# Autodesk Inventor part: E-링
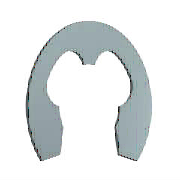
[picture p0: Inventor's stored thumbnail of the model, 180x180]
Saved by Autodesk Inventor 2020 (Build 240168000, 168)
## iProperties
IsCustomPart: 1
Created: 2012-02
Part Number: E-링
Material: 강철, 연강
Description: 일반용 테이퍼 및 줄어든 횡단면 리테이닝 링 - E-링 외부 시리즈 3CM1 리테이닝 링
Document SubType Name: Modeling
Standard: ANSI B27.7
Designer: mduedu
Standard Revision: 1999
Standards Organization: ANSI
Language: ko-KR
Size Designation: 6
Categories: <MemberInstance><Categories><Category DisplayName="샤프트 부품" InternalName="7f7aeb1f-a693-4053-b835-cee3144e0d98" Mnemonic="SHFT"><Category DisplayName="써클립" Inter
Density: 1 g/cm^3
Appearance: 파란색 - 벽 페인트 - 광택
Author: mduedu
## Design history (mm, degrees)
sketch "스케치1"
  geometry: L1 (-0.485, 0.024)-(0, 0.024) reference; L2 (-3.206, 0)-(3.486, 0) reference; L3 (-2.223, -3.946)-(2.223, -3.946); L4 (0, 1.949)-(0, -3.479) reference; L5 (-2.91, -2.006)-(-2.435, -2.006); L6 (-0.485, -0.066)-(-0.485, 0.405); L7 (0, 2.574)-(2.53, 2.574); L8 (-2.223, -3.946)-(-3.022, -6.291); L9 (0, -0.551)-(-1.278, -0.551); L10 (2.223, -3.946)-(3.022, -6.291); L11 (2.91, -2.006)-(2.435, -2.006); L12 (0.485, -0.066)-(0.485, 0.405); C1 r 3 at (0, -2.976); A1 r 2.425 centre (0, -2.976) between (-2.297, -2.199) and (-2.223, -3.946); A2 r 0.485 centre (0, -0.066) between (-0.485, -0.066) and (0.485, -0.066); A3 r 5.55 centre (0, -2.976) between (4.27, -6.521) and (-4.27, -6.521); A4 r 3.88 centre (0, -2.976) between (-0.97, 0.78) and (-3.424, -1.15); A5 r 0.388 centre (-0.873, 0.405) between (-0.485, 0.405) and (-0.97, 0.78); A6 r 0.582 centre (-2.91, -1.424) between (-3.424, -1.15) and (-2.91, -2.006); A7 r 0.145 centre (-2.435, -2.152) between (-2.297, -2.199) and (-2.435, -2.006); A8 r 0.727 centre (-3.711, -6.057) between (-4.27, -6.521) and (-3.022, -6.291); A9 r 0.727 centre (3.711, -6.057) between (3.022, -6.291) and (4.27, -6.521); A10 r 2.425 centre (0, -2.976) between (2.223, -3.946) and (2.297, -2.199); A11 r 0.145 centre (2.435, -2.152) between (2.435, -2.006) and (2.297, -2.199); A12 r 0.582 centre (2.91, -1.424) between (2.91, -2.006) and (3.424, -1.15); A13 r 3.88 centre (0, -2.976) between (3.424, -1.15) and (0.97, 0.78); A14 r 0.388 centre (0.873, 0.405) between (0.97, 0.78) and (0.485, 0.405); 1 further point
  constraints: 30 point on circle, 20 end point, 15 centre point, 13 symmetric about line, 12 tangent, 8 point on line, 4 parallel, 2 coincident, 2 horizontal, 1 concentric, 1 perpendicular, 1 vertical alignment, 9 other
  dimensions: "d0" = 6 diameter of C1 (= WD); "d3" = 0.97 distance from line of A1.centre L3 (= 0.2 x ND); "d4" = 0.485 radius of A2 (= 0.1 x ND); "d5" = 11.1 diameter of A3 (= SD2); "d8" = 3.88 radius of A4 (= 0.8 x ND); "d9" = 0.97 distance from line of A1.centre L5 (= 0.2 x ND); "d10" = 0.388 radius of A5 (= 0.08 x ND); "d11" = 0.582 radius of A6 (= 0.12 x ND); "d12" = 0.1455 radius of A7 (= 0.03 x ND); "d13" = 0.7275 radius of A8 (= 0.15 x ND); "d14" = 2.425 distance from line of A1.centre L9 (= 0.5 x ND); "d15" = 2.425 radius of A1 (= 0.5 x ND)
extrude "본체" new body sketch "스케치1" distance "d16" = 0.6 (= SD); taper "d17" = 0 deg
workaxis "Work Axis1"
workaxis "Work Axis2"
workplane "Work Plane1"
body "Solid1"
other parameters: "ND" = 4.85 [user parameter; used in 14 equation terms], "SD" = 0.6 [user parameter; used in 1 equation term], "WD" = 6 (= WDMIN) [user parameter; used in 1 equation term], "d1" = 7.76 (= 1.6 x ND), "d2" = 4.85 (= ND), "SD2" = 11.1 [user parameter; used in 1 equation term], "d6" = 4.85 (= ND), "d7" = 0.7275 (= 0.15 x ND), "d18" = 0, "d19" = 0, "d27" = 0, "d28" = 0, "WDMIN" = 6 [user parameter; used in 1 equation term], "SNB" = 0.7 [user parameter], "WDMAX" = 7 [user parameter], "BUBRMI" = 1.2 [user parameter]
